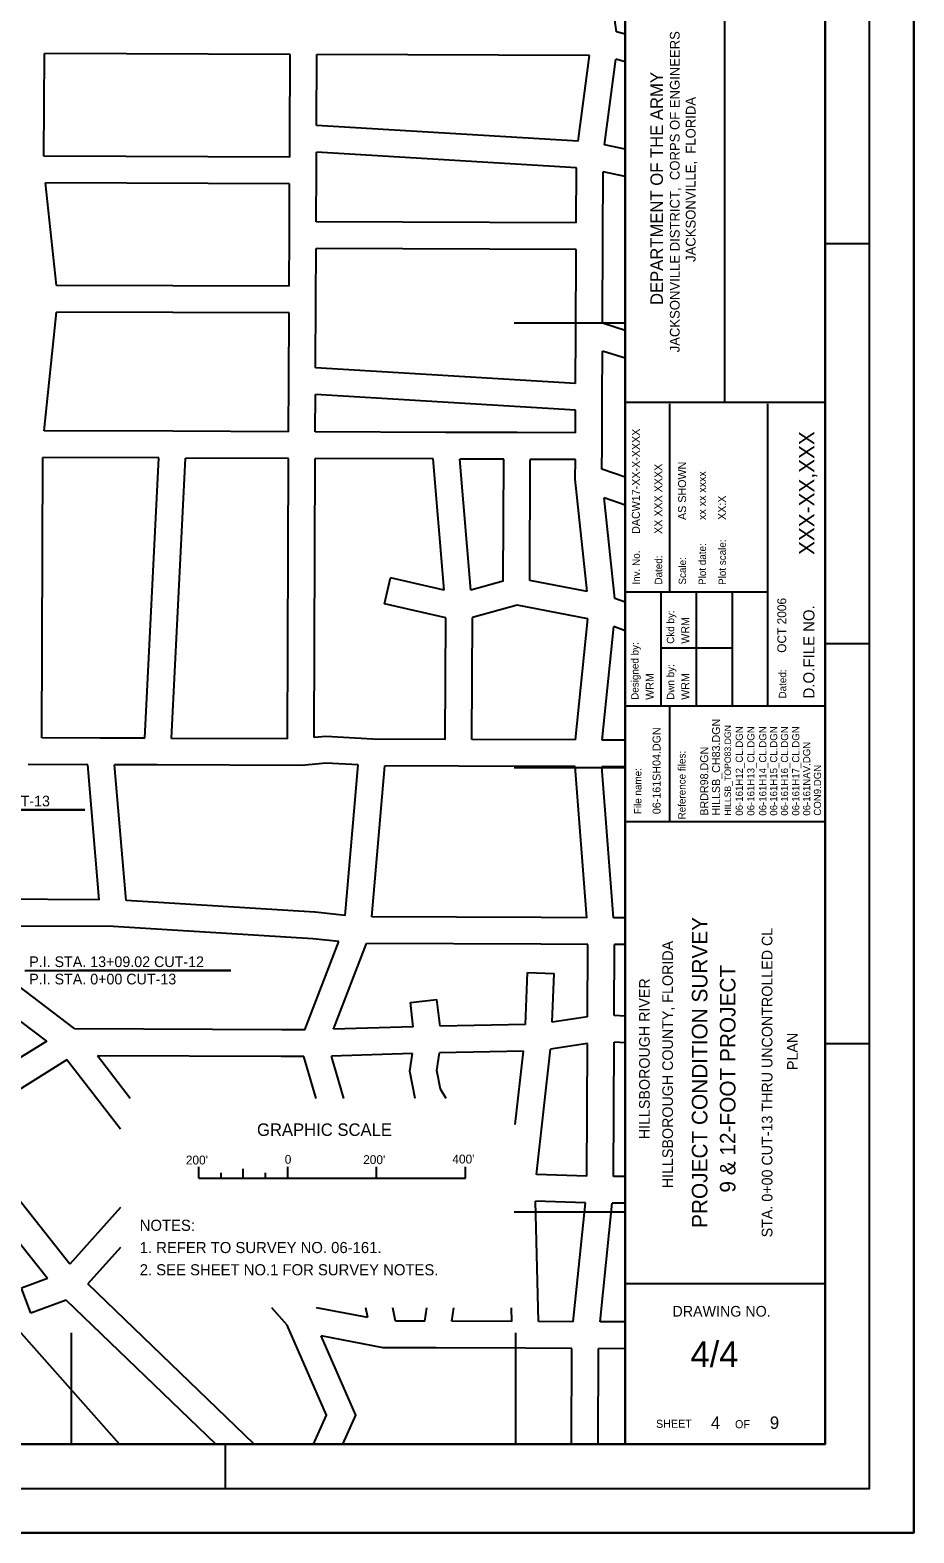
# Model space of a CAD drawing. Extents: x 497696 to 505896, y 1319278 to 1325078.
# Drawn here: x 503906 to 505896, y 1319278 to 1322658 of the extents above; entities that cross this region are included whole.
import ezdxf

# ---------------------------------------------------------------- set-up
doc = ezdxf.new("R2010")
doc.units = 0
for name, color, linetype in [('G-ANNO-TEXT', 7, 'Continuous'), ('G-ANNO-TTLB', 7, 'Continuous'), ('Level 1', 7, 'Continuous'), ('Level 2', 7, 'Continuous'), ('Level 32', 7, 'Continuous'), ('Level 5', 7, 'Continuous'), ('Level 56', 7, 'Continuous'), ('Level 6', 7, 'Continuous')]:
    doc.layers.add(name, color=color, linetype=linetype)

msp = doc.modelspace()

# ---------------------------------------------------------------- linework, layer by layer
at = {"layer": 'G-ANNO-TTLB'}
for p, q in [((505796.2, 1319377.9), (505796.2, 1324977.9)), ((505246.2, 1319477.9), (505246.2, 1324877.9)), ((505696.2, 1324877.9), (505696.2, 1319477.9)), ((505469.6, 1322860.5), (505469.6, 1321820.7)), ((505796.2, 1322177.9), (505696.2, 1322177.9)), ((505696.2, 1321820.7), (505246.2, 1321820.7)), ((505345.8, 1321817.9), (505345.8, 1321394.1)), ((505566.6, 1321817.9), (505566.6, 1321137.9)), ((505566.6, 1321394.1), (505246.2, 1321394.1)), ((505326.4, 1321394.1), (505326.4, 1321137.9)), ((505406.2, 1321394.1), (505406.2, 1321137.9)), ((505486.6, 1321394.1), (505486.6, 1321137.9)), ((505486.6, 1321268.3), (505326.4, 1321268.3)), ((505796.2, 1321277.9), (505696.2, 1321277.9)), ((505696.2, 1321137.9), (505246.2, 1321137.9)), ((505345.8, 1321137.9), (505345.8, 1320877.7)), ((505696.2, 1320877.7), (505246.2, 1320877.7)), ((505796.2, 1320377.9), (505696.2, 1320377.9)), ((505696.2, 1319837.9), (505246.2, 1319837.9)), ((505696.2, 1319477.9), (498046.2, 1319477.9)), ((504346.2, 1319377.9), (504346.2, 1319477.9)), ((497796.2, 1319377.9), (505796.2, 1319377.9))]:
    msp.add_line(p, q, dxfattribs=at)
for points in [[(497696.2, 1319277.9), (505896.2, 1319277.9), (505896.2, 1325077.9), (497696.2, 1325077.9)], [(497696.2, 1319277.9), (505896.2, 1319277.9), (505896.2, 1325077.9), (497696.2, 1325077.9)], [(497696.2, 1325077.9), (505896.2, 1325077.9), (505896.2, 1319277.9), (497696.2, 1319277.9)]]:
    msp.add_lwpolyline(points, close=True, dxfattribs=at)
msp.add_lwpolyline([(505846.2, 1319277.9), (505896.2, 1319277.9), (505896.2, 1319327.9)], dxfattribs=at)
at = {"layer": 'Level 1'}
for p, q in [((505246.2, 1324877.9), (505246.2, 1319477.9)), ((505796.2, 1322177.9), (505696.2, 1322177.9)), ((505796.2, 1321277.9), (505696.2, 1321277.9)), ((505796.2, 1320377.9), (505696.2, 1320377.9)), ((504286.4, 1320076.1), (504286.4, 1320101.2)), ((504486.4, 1320076.1), (504486.4, 1320101.2)), ((504486.4, 1320076.1), (504486.4, 1320101.2)), ((504686.4, 1320076.1), (504686.4, 1320101.2)), ((504886.4, 1320076.1), (504886.4, 1320101.2)), ((504286.4, 1320076.1), (504886.5, 1320076.1)), ((504336.4, 1320076.6), (504336.4, 1320088.1)), ((504386.4, 1320076.1), (504386.4, 1320096.6)), ((504386.4, 1320076.6), (504386.4, 1320088.1)), ((504436.4, 1320076.6), (504436.4, 1320088.1)), ((504486.4, 1320076.1), (504486.4, 1320088.1)), ((504346.2, 1319377.9), (504346.2, 1319477.9))]:
    msp.add_line(p, q, dxfattribs=at)
for points in [[(497796.2, 1319377.9), (505796.2, 1319377.9), (505796.2, 1324977.9), (497796.2, 1324977.9)], [(498046.2, 1319477.9), (505696.2, 1319477.9), (505696.2, 1324877.9), (498046.2, 1324877.9)]]:
    msp.add_lwpolyline(points, close=True, dxfattribs=at)
at = {"layer": 'Level 2'}
for p, q in [((504996.2, 1322000), (505246.2, 1322000)), ((504996.2, 1321000), (505246.2, 1321000)), ((504996.2, 1320000), (505246.2, 1320000)), ((504000, 1319477.9), (504000, 1319727.9)), ((505000, 1319477.9), (505000, 1319727.9))]:
    msp.add_line(p, q, dxfattribs=at)
at = {"layer": 'Level 32'}
for p, q in [((505226.8, 1322654.6), (505204.3, 1322810.3)), ((505246.2, 1322649), (505226.8, 1322654.6)), ((503937.7, 1322375.1), (503938.6, 1322605.9)), ((504491.9, 1322603.8), (503938.6, 1322605.9)), ((504491.1, 1322415.6), (504491.9, 1322603.8)), ((504551.2, 1322443.8), (504551.9, 1322603.5)), ((505165.7, 1322601.2), (504551.9, 1322603.5)), ((505140.5, 1322408.3), (505165.7, 1322601.2)), ((505199.9, 1322400.4), (505225.1, 1322592.7)), ((505246.2, 1322586.6), (505225.1, 1322592.7)), ((505140.5, 1322408.3), (504551.2, 1322443.8)), ((504491, 1322372.9), (504491.1, 1322415.6)), ((505246.2, 1322390.7), (505199.9, 1322400.4)), ((504491, 1322372.9), (503937.7, 1322375.1)), ((504550.9, 1322342.7), (504551, 1322383.7)), ((505136.5, 1322348.5), (504551, 1322383.7)), ((504550.4, 1322227.3), (504550.9, 1322342.7)), ((505136, 1322225), (505136.5, 1322348.5)), ((505195.9, 1322194.8), (505196.4, 1322339.8)), ((505246.2, 1322329.4), (505196.4, 1322339.8)), ((503965.7, 1322084.1), (503941, 1322315)), ((504490.7, 1322312.9), (503941, 1322315)), ((504490.3, 1322197.5), (504490.7, 1322312.9)), ((505136, 1322225), (504550.4, 1322227.3)), ((504489.9, 1322082.1), (504490.3, 1322197.5)), ((505195.1, 1321998.9), (505195.9, 1322194.8)), ((504549.7, 1322051.9), (504550.2, 1322167.3)), ((505135.8, 1322165), (504550.2, 1322167.3)), ((505135, 1321976.9), (505135.8, 1322165)), ((504489.9, 1322082.1), (503965.7, 1322084.1)), ((503938.4, 1321757), (503965.8, 1322024.1)), ((504489.6, 1322022.1), (503965.8, 1322024.1)), ((504549.1, 1321898.4), (504549.7, 1322051.9)), ((504489, 1321870.3), (504489.6, 1322022.1)), ((505246.2, 1321982.9), (505195.1, 1321998.9)), ((505134.6, 1321863.2), (505135, 1321976.9)), ((505194.5, 1321831.3), (505194.9, 1321936.1)), ((505246.2, 1321920.1), (505194.9, 1321936.1)), ((505134.6, 1321863.2), (504549.1, 1321898.4)), ((504488.6, 1321754.9), (504489, 1321870.3)), ((504548.6, 1321754.7), (504548.9, 1321838.4)), ((505134.4, 1321803.1), (504548.9, 1321838.4)), ((505194.1, 1321722.2), (505194.5, 1321831.3)), ((505134.2, 1321752.4), (505134.4, 1321803.1)), ((504228.1, 1321755.9), (503938.4, 1321757)), ((504488.6, 1321754.9), (504228.1, 1321755.9)), ((504841.4, 1321753.5), (504548.6, 1321754.7)), ((505002.8, 1321752.9), (504841.4, 1321753.5)), ((505134.2, 1321752.4), (505002.8, 1321752.9)), ((505193.9, 1321671), (505194.1, 1321722.2)), ((503932.6, 1321066.3), (503935.1, 1321697)), ((504196.4, 1321696), (503935.1, 1321697)), ((504164.5, 1321065.4), (504196.4, 1321696)), ((504224.6, 1321065.2), (504256.5, 1321695.8)), ((504488.4, 1321694.9), (504256.5, 1321695.8)), ((504485.9, 1321064.1), (504488.4, 1321694.9)), ((504546, 1321067.1), (504548.4, 1321694.7)), ((504813.7, 1321693.6), (504548.4, 1321694.7)), ((504838.8, 1321398.3), (504813.7, 1321693.6)), ((504972.6, 1321693), (504873.9, 1321693.4)), ((504899, 1321398.4), (504873.9, 1321693.4)), ((504971.5, 1321418.6), (504972.6, 1321693)), ((505031.5, 1321420.5), (505032.6, 1321692.8)), ((505134, 1321692.4), (505032.6, 1321692.8)), ((505133.8, 1321648.1), (505134, 1321692.4)), ((505246.2, 1321653.1), (505193.9, 1321671)), ((505160.8, 1321395.7), (505133.8, 1321648.1)), ((505246.2, 1321589.7), (505198.6, 1321606)), ((505222.8, 1321380.1), (505198.6, 1321606)), ((504704.2, 1321367.6), (504717.6, 1321426.1)), ((504838.8, 1321398.3), (504717.6, 1321426.1)), ((504971.5, 1321418.6), (504899, 1321398.4)), ((505160.8, 1321395.7), (505031.5, 1321420.5)), ((504842.1, 1321336), (504704.2, 1321367.6)), ((505002.7, 1321364.9), (504902.1, 1321337)), ((505162.3, 1321334.3), (505002.7, 1321364.9)), ((505246.2, 1321371.3), (505222.8, 1321380.1)), ((504841, 1321062.8), (504842.1, 1321336)), ((504901, 1321062.6), (504902.1, 1321337)), ((505134.4, 1321061.7), (505162.3, 1321334.3)), ((505194.6, 1321061.4), (505220.8, 1321316.7)), ((505246.2, 1321307.1), (505220.8, 1321316.7)), ((504064, 1321065.8), (503932.6, 1321066.3)), ((504164.5, 1321065.4), (504064, 1321065.8)), ((504485.9, 1321064.1), (504224.6, 1321065.2)), ((504572.1, 1321069.7), (504546, 1321067.1)), ((504678.2, 1321063.4), (504572.1, 1321069.7)), ((504841, 1321062.8), (504678.2, 1321063.4)), ((505134.4, 1321061.7), (504901, 1321062.6)), ((505246.2, 1321061.2), (505194.6, 1321061.4)), ((504036.3, 1321005.9), (503902.4, 1321006.4)), ((504062.1, 1320702.2), (504036.3, 1321005.9)), ((504192.9, 1321005.3), (504096.6, 1321005.6)), ((504122.5, 1320700.4), (504096.6, 1321005.6)), ((504517.2, 1321004), (504192.9, 1321005.3)), ((504573.2, 1321009.5), (504517.2, 1321004)), ((504644.7, 1321005.3), (504573.2, 1321009.5)), ((504616.1, 1320666.7), (504644.7, 1321005.3)), ((504676, 1320663.5), (504704.8, 1321003.3)), ((504870.8, 1321002.7), (504704.8, 1321003.3)), ((505133.6, 1321001.7), (504870.8, 1321002.7)), ((505159.8, 1320661.7), (505133.6, 1321001.7)), ((505220, 1320661.4), (505193.8, 1321001.4)), ((505246.2, 1321001.2), (505193.8, 1321001.4)), ((504062.1, 1320702.2), (503690.7, 1320703.7)), ((504547.8, 1320674.1), (504122.5, 1320700.4)), ((504616.1, 1320666.7), (504547.9, 1320674.1)), ((504093.8, 1320642.1), (503721.2, 1320643.5)), ((504542.8, 1320614.3), (504093.8, 1320642.1)), ((505056.7, 1320662.1), (504676, 1320663.5)), ((505159.8, 1320661.7), (505056.7, 1320662.1)), ((505246.2, 1320661.3), (505220, 1320661.4)), ((504006.9, 1320411.6), (503731.5, 1320620.1)), ((504525, 1320409.6), (504601.4, 1320608)), ((504601.4, 1320608), (504542.8, 1320614.3)), ((504589.8, 1320410.9), (504664, 1320603.6)), ((505056.5, 1320602.1), (504664, 1320603.6)), ((505162.1, 1320601.6), (505056.5, 1320602.1)), ((505161.4, 1320439.2), (505162.1, 1320601.6)), ((505221.4, 1320441.6), (505222.1, 1320601.4)), ((505246.2, 1320601.3), (505222.1, 1320601.4)), ((503943.9, 1320384.1), (503702.2, 1320567)), ((505021.6, 1320421.6), (505026.3, 1320538.7)), ((505026.3, 1320538.7), (505086.2, 1320536.3)), ((505081.9, 1320427.2), (505086.2, 1320536.3)), ((504762.8, 1320471.1), (504822.4, 1320478)), ((504769.1, 1320416.3), (504762.8, 1320471.1)), ((504829.3, 1320417.8), (504822.4, 1320478)), ((505161.4, 1320439.2), (505081.9, 1320427.2)), ((505246.2, 1320440.2), (505221.4, 1320441.6)), ((504472.1, 1320409.8), (504006.9, 1320411.6)), ((504525, 1320409.6), (504472.1, 1320409.8)), ((504769.1, 1320416.3), (504589.8, 1320410.9)), ((505021.6, 1320421.6), (504829.3, 1320417.8)), ((503943.9, 1320384.1), (503710.1, 1320239.1)), ((505161.2, 1320378.5), (505077.8, 1320365.9)), ((505160.1, 1320080.7), (505161.2, 1320378.5)), ((505220.1, 1320079.7), (505221.2, 1320381.6)), ((505246.2, 1320380), (505221.2, 1320381.6)), ((503989.6, 1320341.8), (503750, 1320193.2)), ((504109.7, 1320186.1), (503989.6, 1320341.8)), ((504132.1, 1320255.2), (504058, 1320351.4)), ((504471.9, 1320349.8), (504058, 1320351.4)), ((504523.1, 1320349.6), (504471.9, 1320349.8)), ((504550.6, 1320255.2), (504523.1, 1320349.6)), ((504767.5, 1320356.2), (504585.3, 1320350.7)), ((504613.1, 1320255.2), (504585.3, 1320350.7)), ((505016.9, 1320361.5), (504828.4, 1320357.8)), ((504998.6, 1320196.5), (505016.9, 1320361.5)), ((505046.5, 1320084), (505077.8, 1320365.9)), ((503945.5, 1319850.1), (503683.1, 1320181)), ((503996.1, 1319882.8), (503750, 1320193.2)), ((505160.1, 1320080.7), (505046.5, 1320084)), ((505246.2, 1320079.6), (505220.1, 1320079.7)), ((504109.7, 1320009.8), (503996.1, 1319882.8)), ((505051.3, 1319753.2), (505043.9, 1320024)), ((505156.8, 1320020.8), (505043.9, 1320024)), ((505129.3, 1319752.9), (505156.8, 1320020.8)), ((505189.6, 1319752.7), (505217, 1320019.7)), ((505246.2, 1320019.6), (505217, 1320019.7)), ((504109.7, 1319919.8), (504036.4, 1319837.9)), ((503945.5, 1319850.1), (503887.3, 1319828.4)), ((503908.2, 1319772.2), (503887.3, 1319828.4)), ((504411.2, 1319477.9), (504036.4, 1319837.9)), ((503987.5, 1319801.6), (503908.2, 1319772.2)), ((504324.6, 1319477.9), (503987.5, 1319801.6)), ((504485.3, 1319745.3), (504450.8, 1319784.5)), ((504666.6, 1319762.3), (504550.9, 1319784.5)), ((504666.6, 1319762.3), (504662.3, 1319784.5)), ((504729.3, 1319754.4), (504723.4, 1319784.5)), ((504991.3, 1319753.4), (504990.4, 1319784.5)), ((504794.9, 1319754.2), (504729.3, 1319754.4)), ((504991.3, 1319753.4), (504855.6, 1319753.9)), ((505129.3, 1319752.9), (505051.3, 1319753.2)), ((505246.2, 1319752.4), (505189.6, 1319752.7)), ((504701.6, 1319694.5), (504561.4, 1319721.4)), ((504820.6, 1319694.1), (504701.6, 1319694.5)), ((505022, 1319693.3), (504820.6, 1319694.1)), ((505126.3, 1319692.9), (505022, 1319693.3)), ((505125.5, 1319477.9), (505126.3, 1319692.9)), ((505185.5, 1319477.9), (505186.3, 1319692.7)), ((505246.2, 1319692.4), (505186.3, 1319692.7))]:
    msp.add_line(p, q, dxfattribs=at)
for points in [[(504773.5, 1320255.2), (504761.5, 1320316.9), (504767.5, 1320356.2)], [(504843.4, 1320255.2), (504830.5, 1320276.2), (504822.4, 1320318.1), (504828.4, 1320357.8)], [(504794.9, 1319754.2), (504799.5, 1319784.5)], [(504855.6, 1319753.9), (504860.2, 1319784.5)], [(504544.8, 1319477.9), (504574.1, 1319543.2), (504485.3, 1319745.3)], [(504610.6, 1319477.9), (504639.8, 1319543), (504561.4, 1319721.4)]]:
    msp.add_lwpolyline(points, dxfattribs=at)
at = {"layer": 'Level 5'}
msp.add_lwpolyline([(504107.7, 1319477.9), (503822.6, 1319798.4), (503531.7, 1320041), (503232.9, 1320458.6), (503199.8, 1320550.4), (502737.7, 1321243.7), (502440.6, 1321661.5), (502255.8, 1321845.1), (502052.9, 1321934.2), (501254.5, 1322198), (501046.8, 1322407), (500972.3, 1322582.2), (500898.1, 1322849.2), (500933, 1323374.1), (501045.4, 1323950.4), (501078.5, 1324015.1), (501460.9, 1324322.7), (501588.1, 1324548.9), (501884.4, 1324877.9)], dxfattribs=at)
at = {"layer": 'Level 56'}
for p, q in [((503565.8, 1320904.8), (504029.7, 1320904.8)), ((504029.7, 1320904.8), (503684, 1320904.8)), ((503894.6, 1320543.3), (504358.6, 1320543.3)), ((504358.6, 1320543.3), (504012.9, 1320543.3))]:
    msp.add_line(p, q, dxfattribs=at)

# ---------------------------------------------------------------- texts
at = {"layer": 'G-ANNO-TEXT'}
for s, height, rotation, p in [('JACKSONVILLE DISTRICT,  CORPS OF ENGINEERS', 21.998, 90, (505368.8, 1321933.5)), ('DEPARTMENT OF THE ARMY', 27.998, 90, (505331, 1322039.9)), ('JACKSONVILLE,  FLORIDA', 21.998, 90, (505404.6, 1322136.9)), ('Inv. No.', 16.6, 90, (505279.2, 1321411.1)), ('Plot date:', 16.6, 90, (505428, 1321410.3)), ('Plot scale: ', 16.6, 90, (505472.8, 1321410.3)), ('Dated:', 16.6, 90, (505329.4, 1321411.1)), ('Scale:', 16.6, 90, (505383.2, 1321411.1)), ('Ckd by:', 16.6, 90, (505356.4, 1321277.9)), ('D.O.FILE NO.', 25.2, 90, (505672.2, 1321154.9)), ('Designed by:', 16.6, 90, (505276.2, 1321151.9)), ('Dwn by:', 16.6, 90, (505356.4, 1321151.9)), ('Dated:', 16.6, 90, (505608.6, 1321154.9)), ('Reference files:', 16.6, 90.0009, (505382, 1320882.9)), ('File name:', 16.6, 90.0009, (505282.8, 1320894.7))]:
    msp.add_text(s, height=height, rotation=rotation, dxfattribs=at).set_placement(p)
msp.add_text('DRAWING NO.', height=24, dxfattribs=at).set_placement((505352.6, 1319764.5))
at = {"layer": 'Level 1'}
for s, height, p in [('GRAPHIC SCALE', 28, (504417.3, 1320171)), ("200'", 20, (504257.1, 1320106.7)), ('0', 20, (504479.8, 1320108.3)), ("200'", 20, (504656.3, 1320107.6)), ("400'", 20, (504857.1, 1320108.9)), ('NOTES:', 25, (504153.3, 1319957.4)), ('1. REFER TO SURVEY NO. 06-161.', 25, (504153.3, 1319907.4)), ('2. SEE SHEET NO.1 FOR SURVEY NOTES.', 25, (504153.3, 1319857.4))]:
    msp.add_text(s, height=height, dxfattribs=at).set_placement(p)
at = {"layer": 'Level 5'}
for s, height, rotation, p in [('AS SHOWN', 18, 90.0009, (505383.2, 1321556.5)), ('xx xx xxxx', 18, 90.0009, (505428, 1321556.5)), ('XX:X', 18, 90.0009, (505472.8, 1321556.5)), ('WRM', 18, 90.001, (505390.2, 1321277.9)), ('WRM', 18, 90.001, (505310.4, 1321151.9)), ('WRM', 18, 90.001, (505390.2, 1321151.9)), ('06-161SH04.DGN', 18, 90.0009, (505325.8, 1320894.7)), ('HILLSB_CH83.DGN', 18, 90.0009, (505459.7, 1320891.3)), ('HILLSB_TOPO83.DGN', 14.58, 90.0009, (505484.3, 1320891.3)), ('06-161H12_CL.DGN', 16.2, 90.0009, (505511, 1320891.3)), ('06-161H13_CL.DGN', 16.2, 90.0009, (505537.1, 1320891.3)), ('06-161H14_CL.DGN', 16.2, 90.0009, (505563.9, 1320891.3)), ('06-161H15_CL.DGN', 16.2, 90.0009, (505588.4, 1320891.3)), ('06-161H16_CL.DGN', 16.2, 90.0009, (505612.9, 1320891.3)), ('06-161H17_CL.DGN', 16.2, 90.0009, (505638.2, 1320891.3)), ('06-161NAV.DGN', 16.2, 90.0009, (505662.7, 1320891.3)), ('CON9.DGN', 16.2, 90.0009, (505687.1, 1320891.3)), ('SHEET', 18.1, 0.34, (505315.6, 1319514.3))]:
    msp.add_text(s, height=height, rotation=rotation, dxfattribs=at).set_placement(p)
for s, height, p in [('4/4', 58, (505393.3, 1319651.1)), ('4', 28, (505439.2, 1319511.9)), ('OF', 18.11, (505493.4, 1319513.5)), ('9', 28, (505571.8, 1319511.9))]:
    msp.add_text(s, height=height, dxfattribs=at).set_placement(p)
at = {"layer": 'Level 56'}
for s, p in [('P.I. STA. 3+00.00 CUT-13', (503575.7, 1320912.3)), ('P.I. STA. 13+09.02 CUT-12', (503904.6, 1320550.8)), ('P.I. STA. 0+00 CUT-13', (503904.6, 1320511.8))]:
    msp.add_text(s, height=24, dxfattribs=at).set_placement(p)
at = {"layer": 'Level 6'}
for s, height, rotation, p in [('DACW17-XX-X-XXXX', 17.999, 90.0009, (505279.2, 1321525.1)), ('XXX-XX,XXX', 35, 90, (505672.2, 1321477.7)), ('XX XXX XXXX', 17.999, 90.0009, (505329.4, 1321525.1)), ('OCT 2006', 20, 90, (505608.6, 1321257.7)), ('BRDR98.DGN', 18, 90.0009, (505433, 1320891.3)), ('PROJECT CONDITION SURVEY', 35, 90, (505431.2, 1319964)), ('STA. 0+00 CUT-13 THRU UNCONTROLLED CL', 24, 90, (505577.6, 1319942.8)), ('HILLSBOROUGH COUNTY, FLORIDA', 24, 90, (505353.7, 1320053.3)), ('9 & 12-FOOT PROJECT', 35, 90, (505494.4, 1320043.4)), ('HILLSBOROUGH RIVER', 24, 90, (505301.5, 1320163.5)), ('PLAN', 24, 90, (505634.6, 1320319.1))]:
    msp.add_text(s, height=height, rotation=rotation, dxfattribs=at).set_placement(p)

doc.saveas('drawing.dxf')
